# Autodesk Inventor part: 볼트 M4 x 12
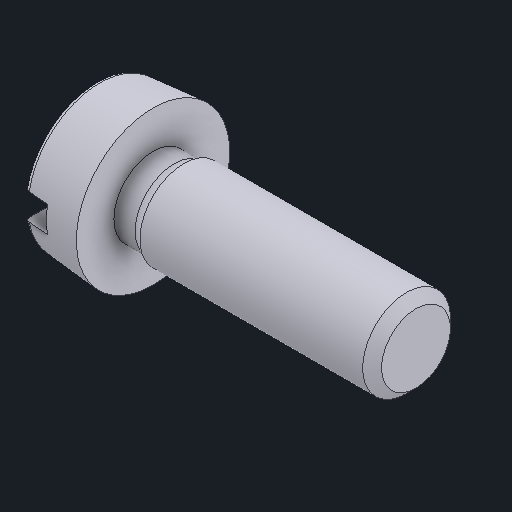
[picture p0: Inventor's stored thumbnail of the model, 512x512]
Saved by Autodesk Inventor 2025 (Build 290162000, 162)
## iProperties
Created: 2025-08
Part Number: 볼트 M4 x 12
Material: 강철, 연강
Description: 6각머리 태핑 나사
Document SubType Name: Modeling
Designer: infra14
Density: 7.85 g/cm^3
Appearance: 기본값
Author: jhkim
Sending System: Autodesk Inventor 2026
Preprocessor: ST-DEVELOPER v20.1
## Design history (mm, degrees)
feature "Solid1"
node "솔리드1"
